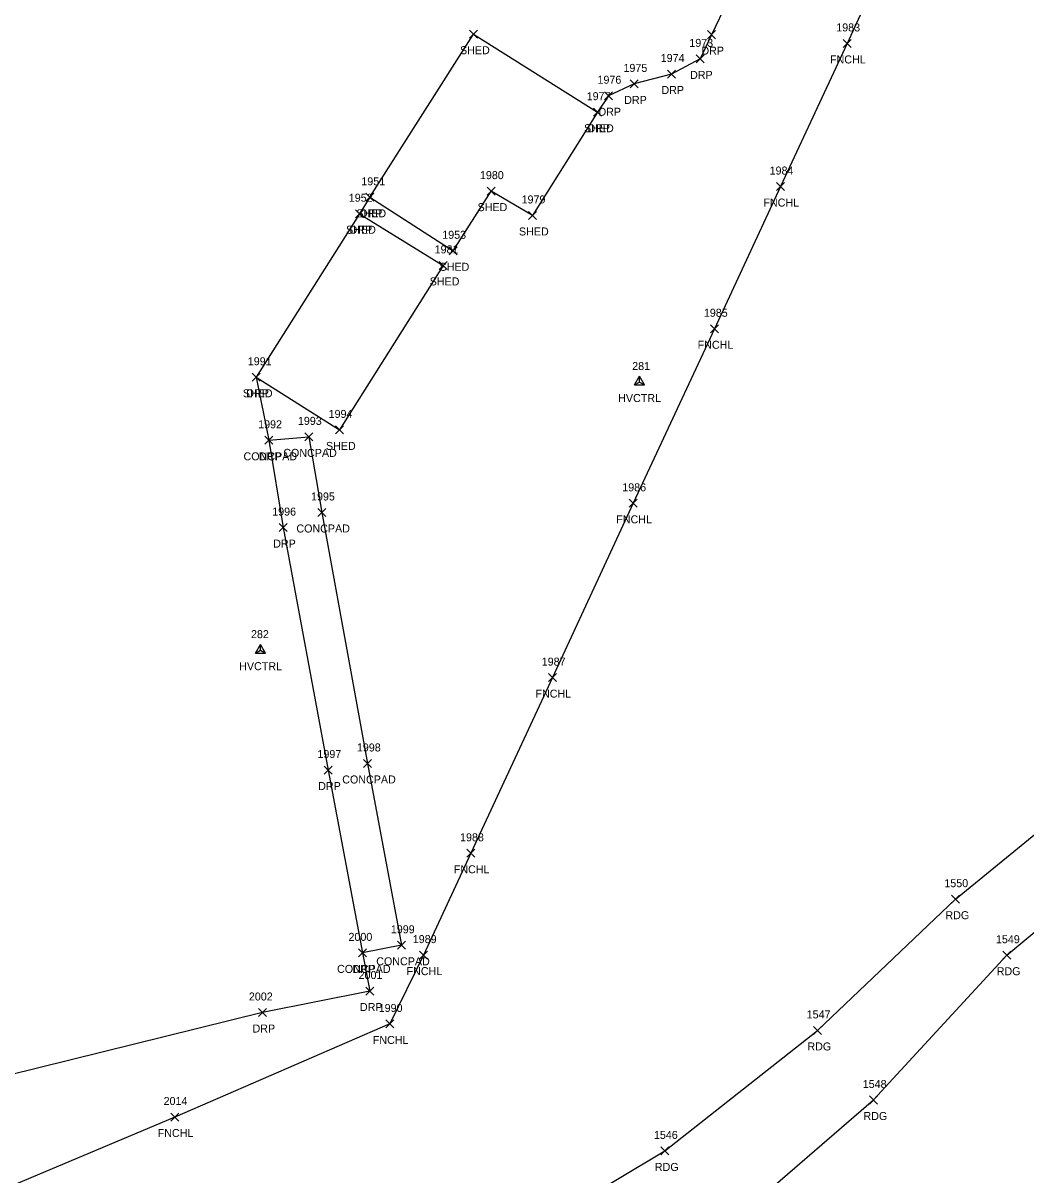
# Model space of a CAD drawing. Extents: x 1481523 to 1489083, y 884156 to 893756.
# Drawn here: x 1486901.6 to 1487152.1, y 888166.7 to 888454.5 of the extents above; entities that cross this region are included whole.
import ezdxf

# ---------------------------------------------------------------- set-up
doc = ezdxf.new("R2010")
doc.units = 0
for name, color, linetype in [('C_A', 7, 'Continuous'), ('C_I', 7, 'Continuous'), ('CPSM', 7, 'Continuous'), ('L_A', 7, 'Continuous'), ('L_I', 7, 'Continuous'), ('L_TIC', 7, 'Continuous'), ('LBC', 7, 'Continuous'), ('LFNC', 7, 'Continuous'), ('LS', 7, 'Continuous'), ('P_A', 7, 'Continuous'), ('P_I', 7, 'Continuous'), ('P_TIC', 7, 'Continuous'), ('PEU', 7, 'Continuous'), ('R_A', 7, 'Continuous'), ('R_I', 7, 'Continuous'), ('R_TIC', 7, 'Continuous'), ('RDP', 7, 'Continuous')]:
    doc.layers.add(name, color=color, linetype=linetype)

msp = doc.modelspace()

# ---------------------------------------------------------------- linework, layer by layer
at = {"layer": 'CPSM'}
for p, q in [((1487054.29, 888364.03), (1487055.54, 888366.2)), ((1487054.29, 888364.03), (1487055.54, 888364.76)), ((1487054.29, 888364.03), (1487056.79, 888364.03)), ((1487056.79, 888364.03), (1487055.54, 888366.2)), ((1487055.54, 888364.76), (1487055.54, 888366.2)), ((1487055.54, 888364.76), (1487055.54, 888364.76)), ((1487055.54, 888364.76), (1487056.79, 888364.03)), ((1486959.64, 888297.05), (1486960.89, 888299.21)), ((1486959.64, 888297.05), (1486960.89, 888297.77)), ((1486962.14, 888297.05), (1486960.89, 888299.21)), ((1486960.89, 888297.77), (1486960.89, 888299.21)), ((1486960.89, 888297.77), (1486960.89, 888297.77)), ((1486960.89, 888297.77), (1486962.14, 888297.05)), ((1486959.64, 888297.05), (1486962.14, 888297.05))]:
    msp.add_line(p, q, dxfattribs=at)
at = {"layer": 'L_TIC'}
for points in [[(1487013.11, 888450.67), (1487015.11, 888452.67)], [(1487015.11, 888450.67), (1487013.11, 888452.67)], [(1487106.41, 888448.36), (1487108.41, 888450.36)], [(1487108.41, 888448.36), (1487106.41, 888450.36)], [(1487044.07, 888431.18), (1487046.07, 888433.18)], [(1487046.07, 888431.18), (1487044.07, 888433.18)], [(1487017.49, 888411.46), (1487019.49, 888413.46)], [(1487019.49, 888411.46), (1487017.49, 888413.46)], [(1487017.49, 888411.46), (1487019.49, 888413.46)], [(1487019.49, 888411.46), (1487017.49, 888413.46)], [(1487089.77, 888412.6), (1487091.77, 888414.6)], [(1487091.77, 888412.6), (1487089.77, 888414.6)], [(1486987.22, 888409.91), (1486989.22, 888411.91)], [(1486989.22, 888409.91), (1486987.22, 888411.91)], [(1486987.22, 888409.91), (1486989.22, 888411.91)], [(1486989.22, 888409.91), (1486987.22, 888411.91)], [(1486984.65, 888405.81), (1486986.65, 888407.81)], [(1486986.65, 888405.81), (1486984.65, 888407.81)], [(1486984.65, 888405.81), (1486986.65, 888407.81)], [(1486986.65, 888405.81), (1486984.65, 888407.81)], [(1487027.83, 888405.38), (1487029.83, 888407.38)], [(1487029.83, 888405.38), (1487027.83, 888407.38)], [(1487008, 888396.55), (1487010, 888398.55)], [(1487010, 888396.55), (1487008, 888398.55)], [(1487005.53, 888392.9), (1487007.53, 888394.9)], [(1487007.53, 888392.9), (1487005.53, 888394.9)], [(1487073.34, 888377.07), (1487075.34, 888379.07)], [(1487075.34, 888377.07), (1487073.34, 888379.07)], [(1486958.85, 888364.95), (1486960.85, 888366.95)], [(1486960.85, 888364.95), (1486958.85, 888366.95)], [(1486979.61, 888351.8), (1486981.61, 888353.8)], [(1486981.61, 888351.8), (1486979.61, 888353.8)], [(1486979.61, 888351.8), (1486981.61, 888353.8)], [(1486981.61, 888351.8), (1486979.61, 888353.8)], [(1486962.01, 888349.2), (1486964.01, 888351.2)], [(1486964.01, 888349.2), (1486962.01, 888351.2)], [(1486971.94, 888350.06), (1486973.94, 888352.06)], [(1486973.94, 888350.06), (1486971.94, 888352.06)], [(1487053.02, 888333.46), (1487055.02, 888335.46)], [(1487055.02, 888333.46), (1487053.02, 888335.46)], [(1486975.23, 888331.17), (1486977.23, 888333.17)], [(1486977.23, 888331.17), (1486975.23, 888333.17)], [(1487032.84, 888289.91), (1487034.84, 888291.91)], [(1487034.84, 888289.91), (1487032.84, 888291.91)], [(1486986.67, 888268.46), (1486988.67, 888270.46)], [(1486988.67, 888268.46), (1486986.67, 888270.46)], [(1487012.45, 888246.02), (1487014.45, 888248.02)], [(1487014.45, 888246.02), (1487012.45, 888248.02)], [(1486985.38, 888221.13), (1486987.38, 888223.13)], [(1486987.38, 888221.13), (1486985.38, 888223.13)], [(1486995.16, 888223.03), (1486997.16, 888225.03)], [(1486997.16, 888223.03), (1486995.16, 888225.03)], [(1487000.64, 888220.58), (1487002.64, 888222.58)], [(1487002.64, 888220.58), (1487000.64, 888222.58)], [(1486992.21, 888203.38), (1486994.21, 888205.38)], [(1486994.21, 888203.38), (1486992.21, 888205.38)], [(1486938.48, 888180.13), (1486940.48, 888182.13)], [(1486940.48, 888180.13), (1486938.48, 888182.13)]]:
    msp.add_lwpolyline(points, dxfattribs=at)
at = {"layer": 'LBC'}
for points in [[(1486988.22, 888410.91), (1487014.11, 888451.67), (1487045.07, 888432.18), (1487028.83, 888406.38), (1487018.49, 888412.46)], [(1486988.22, 888410.91), (1487009, 888397.55), (1487018.49, 888412.46)], [(1486985.65, 888406.81), (1486959.85, 888365.95), (1486980.61, 888352.8)], [(1486985.65, 888406.81), (1487006.53, 888393.9), (1486980.61, 888352.8)]]:
    msp.add_lwpolyline(points, dxfattribs=at)
at = {"layer": 'LFNC'}
msp.add_lwpolyline([(1487123.63, 888696.4), (1487124.91, 888638.27), (1487126.15, 888568.63), (1487127.36, 888492.8), (1487107.41, 888449.36), (1487090.77, 888413.6), (1487074.34, 888378.07), (1487054.02, 888334.46), (1487033.84, 888290.91), (1487013.45, 888247.02), (1487001.64, 888221.58), (1486993.21, 888204.38), (1486939.48, 888181.13), (1486867.52, 888150.81), (1486821.88, 888131.48), (1486777.19, 888112.51), (1486741.33, 888097.33), (1486705.19, 888082.4), (1486701.15, 888103.56), (1486696.51, 888133.19), (1486722.31, 888152.64)], dxfattribs=at)
at = {"layer": 'LS'}
msp.add_lwpolyline([(1486963.01, 888350.2), (1486972.94, 888351.06), (1486976.23, 888332.17), (1486987.67, 888269.46), (1486996.16, 888224.03), (1486986.38, 888222.13)], dxfattribs=at)
at = {"layer": 'P_TIC'}
for points in [[(1487133.5, 888234.55), (1487135.5, 888236.55)], [(1487135.5, 888234.55), (1487133.5, 888236.55)], [(1487146.32, 888220.55), (1487148.32, 888222.55)], [(1487148.32, 888220.55), (1487146.32, 888222.55)], [(1487099.02, 888201.76), (1487101.02, 888203.76)], [(1487101.02, 888201.76), (1487099.02, 888203.76)], [(1487113.03, 888184.38), (1487115.03, 888186.38)], [(1487115.03, 888184.38), (1487113.03, 888186.38)], [(1487060.93, 888171.65), (1487062.93, 888173.65)], [(1487062.93, 888171.65), (1487060.93, 888173.65)]]:
    msp.add_lwpolyline(points, dxfattribs=at)
at = {"layer": 'PEU'}
for points in [[(1486693.43, 888030.65), (1486711.45, 888026.25), (1486729.25, 888026.61), (1486741.64, 888030.11), (1486776.57, 888043.35), (1486813.61, 888057.74), (1486859.9, 888076.88), (1486905.09, 888096.2), (1486933.17, 888108.11), (1486991.44, 888135.23), (1487027.3, 888151.91), (1487061.93, 888172.65), (1487100.02, 888202.76), (1487134.5, 888235.55), (1487174.13, 888267.94)], [(1486703.84, 887971.32), (1486720.57, 887989.63), (1486732.92, 887997.98), (1486752, 888006.2), (1486785.58, 888023.44), (1486824.24, 888039.92), (1486864.7, 888056.22), (1486913.32, 888074.9), (1486944.19, 888087.45), (1487001.42, 888113.78), (1487037.5, 888132.44), (1487077.83, 888154.12), (1487114.03, 888185.38), (1487147.32, 888221.55), (1487184.59, 888252.66)]]:
    msp.add_lwpolyline(points, dxfattribs=at)
at = {"layer": 'R_TIC'}
for points in [[(1487072.55, 888450.55), (1487074.55, 888452.55)], [(1487074.55, 888450.55), (1487072.55, 888452.55)], [(1487069.71, 888444.5), (1487071.71, 888446.5)], [(1487071.71, 888444.5), (1487069.71, 888446.5)], [(1487062.56, 888440.72), (1487064.56, 888442.72)], [(1487064.56, 888440.72), (1487062.56, 888442.72)], [(1487053.26, 888438.24), (1487055.26, 888440.24)], [(1487055.26, 888438.24), (1487053.26, 888440.24)], [(1487046.83, 888435.29), (1487048.83, 888437.29)], [(1487048.83, 888435.29), (1487046.83, 888437.29)], [(1487044.07, 888431.18), (1487046.07, 888433.18)], [(1487046.07, 888431.18), (1487044.07, 888433.18)], [(1486987.22, 888409.91), (1486989.22, 888411.91)], [(1486989.22, 888409.91), (1486987.22, 888411.91)], [(1486984.65, 888405.81), (1486986.65, 888407.81)], [(1486986.65, 888405.81), (1486984.65, 888407.81)], [(1486958.85, 888364.95), (1486960.85, 888366.95)], [(1486960.85, 888364.95), (1486958.85, 888366.95)], [(1486962.01, 888349.2), (1486964.01, 888351.2)], [(1486964.01, 888349.2), (1486962.01, 888351.2)], [(1486965.58, 888327.39), (1486967.58, 888329.39)], [(1486967.58, 888327.39), (1486965.58, 888329.39)], [(1486976.82, 888266.82), (1486978.82, 888268.82)], [(1486978.82, 888266.82), (1486976.82, 888268.82)], [(1486985.38, 888221.13), (1486987.38, 888223.13)], [(1486987.38, 888221.13), (1486985.38, 888223.13)], [(1486987.25, 888211.61), (1486989.25, 888213.61)], [(1486989.25, 888211.61), (1486987.25, 888213.61)], [(1486960.42, 888206.24), (1486962.42, 888208.24)], [(1486962.42, 888206.24), (1486960.42, 888208.24)]]:
    msp.add_lwpolyline(points, dxfattribs=at)
at = {"layer": 'RDP'}
for points in [[(1487077.45, 888459.68), (1487073.55, 888451.55), (1487070.71, 888445.5), (1487063.56, 888441.72), (1487054.26, 888439.24), (1487047.83, 888436.29), (1487045.07, 888432.18)], [(1486988.22, 888410.91), (1486985.65, 888406.81)], [(1486959.85, 888365.95), (1486963.01, 888350.2), (1486966.58, 888328.39), (1486977.82, 888267.82), (1486986.38, 888222.13), (1486988.25, 888212.61), (1486961.42, 888207.24), (1486873.46, 888185.48), (1486827.16, 888176.05), (1486772.66, 888163.88), (1486723.25, 888154.26), (1486717.91, 888152.68), (1486701.43, 888143.32), (1486693.75, 888134.74)]]:
    msp.add_lwpolyline(points, dxfattribs=at)

# ---------------------------------------------------------------- texts
at = {"layer": 'C_A'}
for p in [(1487050.24, 888359.76), (1486955.58, 888292.77)]:
    msp.add_text('HVCTRL', height=2, dxfattribs=at).set_placement(p)
at = {"layer": 'C_I'}
for s, p in [('281', (1487053.75, 888367.76)), ('282', (1486958.53, 888300.77))]:
    msp.add_text(s, height=2, dxfattribs=at).set_placement(p)
at = {"layer": 'L_A'}
for s, p in [('SHED', (1487010.74, 888446.67)), ('FNCHL', (1487103.16, 888444.36)), ('SHED', (1487041.71, 888427.18)), ('FNCHL', (1487086.52, 888408.6)), ('SHED', (1486984.85, 888405.91)), ('SHED', (1486984.85, 888405.91)), ('SHED', (1487015.13, 888407.46)), ('SHED', (1487015.13, 888407.46)), ('SHED', (1486982.29, 888401.81)), ('SHED', (1486982.29, 888401.81)), ('SHED', (1487025.46, 888401.38)), ('SHED', (1487005.63, 888392.55)), ('SHED', (1487003.16, 888388.9)), ('FNCHL', (1487070.09, 888373.07)), ('SHED', (1486956.49, 888360.95)), ('SHED', (1486977.25, 888347.8)), ('SHED', (1486977.25, 888347.8)), ('CONCPAD', (1486956.66, 888345.2)), ('CONCPAD', (1486966.59, 888346.06)), ('CONCPAD', (1486969.87, 888327.17)), ('FNCHL', (1487049.77, 888329.46)), ('FNCHL', (1487029.59, 888285.91)), ('CONCPAD', (1486981.32, 888264.46)), ('FNCHL', (1487009.19, 888242.02)), ('CONCPAD', (1486989.81, 888219.03)), ('CONCPAD', (1486980.03, 888217.13)), ('FNCHL', (1486997.39, 888216.58)), ('FNCHL', (1486988.96, 888199.38)), ('FNCHL', (1486935.22, 888176.13))]:
    msp.add_text(s, height=2, dxfattribs=at).set_placement(p)
at = {"layer": 'L_I'}
for s, p in [('1983', (1487104.72, 888452.36)), ('1977', (1487042.38, 888435.18)), ('1984', (1487088.08, 888416.6)), ('1951', (1486986.09, 888413.91)), ('1951', (1486986.09, 888413.91)), ('1980', (1487015.71, 888415.46)), ('1980', (1487015.71, 888415.46)), ('1952', (1486982.96, 888409.81)), ('1952', (1486982.96, 888409.81)), ('1979', (1487026.12, 888409.38)), ('1953', (1487006.3, 888400.55)), ('1981', (1487004.4, 888396.9)), ('1985', (1487071.65, 888381.07)), ('1991', (1486957.73, 888368.95)), ('1992', (1486960.32, 888353.2)), ('1993', (1486970.25, 888354.06)), ('1994', (1486977.92, 888355.8)), ('1994', (1486977.92, 888355.8)), ('1986', (1487051.27, 888337.46)), ('1995', (1486973.53, 888335.17)), ('1987', (1487031.15, 888293.91)), ('1998', (1486984.98, 888272.46)), ('1988', (1487010.75, 888250.02)), ('1999', (1486993.46, 888227.03)), ('2000', (1486982.88, 888225.13)), ('1989', (1486998.94, 888224.58)), ('1990', (1486990.43, 888207.38)), ('2014', (1486936.7, 888184.13))]:
    msp.add_text(s, height=2, dxfattribs=at).set_placement(p)
at = {"layer": 'P_A'}
for p in [(1487131.99, 888230.55), (1487144.8, 888216.55), (1487097.51, 888197.76), (1487111.52, 888180.38), (1487059.41, 888167.65)]:
    msp.add_text('RDG', height=2, dxfattribs=at).set_placement(p)
at = {"layer": 'P_I'}
for s, p in [('1550', (1487131.72, 888238.55)), ('1549', (1487144.61, 888224.55)), ('1547', (1487097.33, 888205.76)), ('1548', (1487111.34, 888188.38)), ('1546', (1487059.18, 888175.65))]:
    msp.add_text(s, height=2, dxfattribs=at).set_placement(p)
at = {"layer": 'R_A'}
for p in [(1487071.03, 888446.55), (1487068.2, 888440.5), (1487061.05, 888436.72), (1487051.75, 888434.24), (1487045.32, 888431.29), (1487042.56, 888427.18), (1486985.7, 888405.91), (1486983.14, 888401.81), (1486957.34, 888360.95), (1486960.5, 888345.2), (1486964.07, 888323.39), (1486975.31, 888262.82), (1486983.87, 888217.13), (1486985.74, 888207.61), (1486958.91, 888202.24)]:
    msp.add_text('DRP', height=2, dxfattribs=at).set_placement(p)
at = {"layer": 'R_I'}
for s, p in [('1973', (1487068.02, 888448.5)), ('1975', (1487051.57, 888442.24)), ('1974', (1487060.87, 888444.72)), ('1976', (1487045.08, 888439.29)), ('1977', (1487042.38, 888435.18)), ('1951', (1486986.09, 888413.91)), ('1952', (1486982.96, 888409.81)), ('1991', (1486957.73, 888368.95)), ('1992', (1486960.32, 888353.2)), ('1996', (1486963.83, 888331.39)), ('1997', (1486975.13, 888270.82)), ('2000', (1486982.88, 888225.13)), ('2001', (1486985.4, 888215.61)), ('2002', (1486958, 888210.24))]:
    msp.add_text(s, height=2, dxfattribs=at).set_placement(p)

doc.saveas('drawing.dxf')
